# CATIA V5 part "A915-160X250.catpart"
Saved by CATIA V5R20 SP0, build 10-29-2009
Part number: A915-160X250
Source: Unknown
Property "A": "110.000"
Property "ARTICLENO": "A915-160X250"
Property "BOMINFO": "A915-160X250"
Property "CODE": "A915-160X250"
Property "CREATOR": "CADENAS GmbH"
Property "D": "13.500"
Property "D1": "20.000"
Property "FORM": "D"
Property "L": "250.000"
Property "L1": "40.000"
Property "L2": "170.000"
Property "LINA": "A915-160X250"
Property "NB": "A915-160X250"
Property "NBSYN": "$CODE."
Property "NN": "A915"
Property "NT": "VDI 3357 Wear Plates, steel"
Property "SCREW": "M12x25"
Property "SUPPLIER": "CF"
Property "T": "13.000"
Property "W": "160.000"
Bounding box of the stored display mesh (mm): x 0 to 20, y 0 to 250, z -80 to 80
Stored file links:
  C:\Users\borellobunino\Desktop\3D X SITO CF\A915\GSB_OILLESS_G22501160250\CATIAV5\A915-160X250.catpart
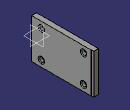
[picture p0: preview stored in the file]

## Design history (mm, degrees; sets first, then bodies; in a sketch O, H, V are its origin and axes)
Body1 "Geometry.1" (main body)
  Solid1 "A915-160X250.catpart": solid without history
